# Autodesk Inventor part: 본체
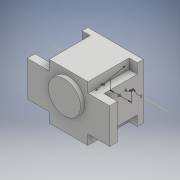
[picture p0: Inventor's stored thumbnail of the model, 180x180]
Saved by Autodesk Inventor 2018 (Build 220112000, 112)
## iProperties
Created: 2020-07
Part Number: 본체
Material: 일반
Document SubType Name: Modeling
Designer: Admin
Density: 1 g/cm^3
Appearance: 기본값
Author: Admin
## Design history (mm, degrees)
sketch "스케치1"
  geometry: L1 (47, -47)-(-47, -47); L2 (-47, -47)-(-47, 47); L3 (-47, 47)-(47, 47); L4 (47, 47)-(47, -47); L5 (47, -47)-(-47, 47); L6 (-47, -47)-(47, 47); 1 further point
  constraints: 12 end point, 2 midpoint, 2 parallel, 1 horizontal, 1 perpendicular
  dimensions: "d0" = 94 distance of L2.end L3.end; "d1" = 94 distance of L1.end L2.end
extrude "돌출1" new body sketch "스케치1" distance "d2" = 80; taper "d3" = 0 deg
sketch "스케치2"
  geometry: L1 (-47, 47)-(-47, -47) reference; L2 (-47, 47)-(-33, 47); L3 (-33, 47)-(-33, 30); L4 (-33, 30)-(-47, 30); L5 (-47, 30)-(-47, 47); L6 (-65.8, 0)-(65.8, 0) reference; L7 (0, -65.8)-(0, 65.8) reference; L8 (47, 47)-(33, 47); L9 (33, 47)-(33, 30); L10 (33, 30)-(47, 30); L11 (47, 30)-(47, 47); L12 (-47, -47)-(-33, -47); L13 (-33, -47)-(-33, -30); L14 (-33, -30)-(-47, -30); L15 (-47, -30)-(-47, -47); L16 (47, -47)-(33, -47); L17 (33, -47)-(33, -30); L18 (33, -30)-(47, -30); L19 (47, -30)-(47, -47); 1 further point
  constraints: 32 end point, 11 symmetric about line, 2 parallel, 1 horizontal, 1 perpendicular
  dimensions: "d4" = 33 distance from line of point (0, 0) L3; "d5" = 30 distance from line of point (0, 0) L4
extrude "돌출2" cut sketch "스케치2" distance "d6" = 70; taper "d7" = 0 deg
sketch "스케치3"
  geometry: L1 (-70, 30)-(70, 30); L2 (70, 30)-(70, -30); L3 (70, -30)-(-70, -30); L4 (-70, -30)-(-70, 30); 1 further point
  constraints: 8 end point, 2 parallel, 1 horizontal, 1 perpendicular
  dimensions: "d8" = 140 distance of L1.start L1.end; "d9" = 60 distance of L1.end L2.end; "d10" = 30 distance from line of L1 point (0, 0); "d11" = 70 distance from line of point (0, 0) L4
extrude "돌출3" join sketch "스케치3" distance "d12" = 13; taper "d13" = 0 deg
sketch "스케치4"
  geometry: L1 (0, -65.8)-(0, 65.8) reference; C1 r 27.5 at (0, 11); 1 further point
  constraints: 1 centre point, 1 point on line
  dimensions: "d14" = 55 diameter of C1; "d15" = 11 distance of point (0, 0) C1.centre
extrude "돌출4" join sketch "스케치4" distance "d16" = 7; taper "d17" = 0 deg
sketch "스케치5"
  geometry: C1 r 43 at (0, 0); 1 further point
  constraints: 1 centre point, 1 coincident
  dimensions: "d18" = 86 diameter of C1
extrude "돌출5" cut sketch "스케치5" distance "d19" = 9; taper "d20" = 0 deg
sketch "스케치6"
  geometry: L1 (-98, 0)-(98, 0) reference; A1 r 40 centre (0, 0) between (-0.053, -40) and (-0.053, 40); A2 r 4 centre (36, 0) between (32, 0) and (36.19, -3.995); A3 r 40 centre (0, 0) between (-0.053, -40) and (39.279, -7.559); A4 r 4 centre (36, 0) between (36.19, 3.995) and (32, 0); A5 r 40 centre (0, 0) between (39.279, 7.559) and (-0.053, 40); A6 r 3 centre (36.333, -6.992) between (39.279, -7.559) and (36.19, -3.995); A7 r 3 centre (36.333, 6.992) between (36.19, 3.995) and (39.279, 7.559); 1 further point
  constraints: 14 point on circle, 7 centre point, 4 tangent, 3 coincident, 2 equal radius, 2 point on line
  dimensions: "d21" = 80 diameter of A1; "d22" = 8 diameter of A2; "d24" = 3 radius of A6; "d25" = 36 distance of point (0, 0) A2.centre
node "솔리드1"
